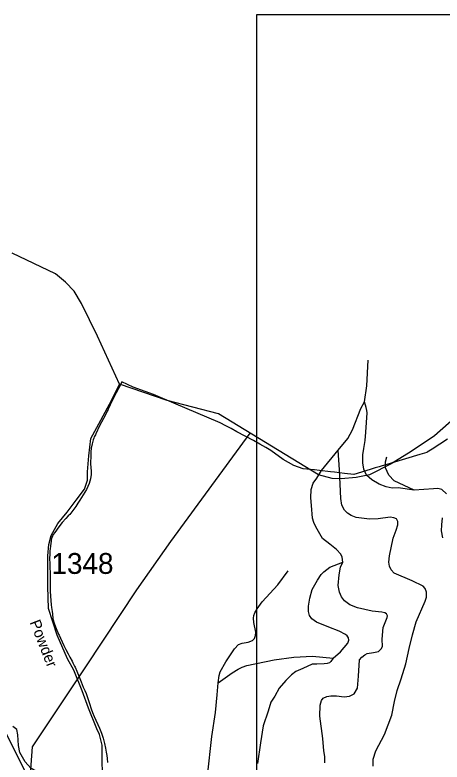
# Model space of a CAD drawing. Extents: x 884530 to 1028605, y 526725 to 653634.
# Drawn here: x 927572 to 930133, y 631169 to 635646 of the extents above; entities that cross this region are included whole.
import ezdxf

# ---------------------------------------------------------------- set-up
doc = ezdxf.new("R2010")
doc.units = 0
for name, color, linetype in [('Exist Boundary Political City Limit New', 7, 'Continuous'), ('Exist Boundary Political CountyLine', 7, 'Continuous'), ('Exist Hydrographic Creek Single Shore', 7, 'Continuous'), ('Exist Road Non-System Type 51', 7, 'Continuous'), ('Exist Road Secondary Type 51 Attributed', 7, 'Continuous'), ('Exist Road Secondary Type 51 Label', 7, 'Continuous'), ('Exist Road Secondary Type 51 Number Label', 7, 'Continuous'), ('Exist Utilities Electrical Transmission Line', 7, 'Continuous'), ('Map Preparation Boundary City Limit Buffer Line', 7, 'Continuous'), ('Map Preparation Inset Cut Line', 7, 'Continuous')]:
    doc.layers.add(name, color=color, linetype=linetype)

msp = doc.modelspace()

# ---------------------------------------------------------------- linework, layer by layer
at = {"layer": 'Exist Boundary Political City Limit New'}
for points in [[(929398.7, 632916.3), (929367.1, 632919.9), (929365.5, 632920.6), (929364.5, 632921.1), (929344, 632922.8), (929300.4, 632926.7), (929244.4, 632946.3), (929179.6, 632981.4), (929106.4, 633035.1), (929075.4, 633054.1), (929057.7, 633065), (929040.5, 633074.2), (929001.1, 633095.4), (928902.8, 633148.2), (928868.1, 633166.9), (928837.1, 633183.6), (928802.6, 633202.1), (928524, 633319.6), (928401.6, 633371.2), (928280.4, 633415.6), (928212.2, 633446.6), (928207.7, 633437.9), (928192.1, 633407.9), (928165.1, 633355.4), (928154.2, 633333.2), (928143.6, 633310.2), (928131.1, 633283.6), (928129.9, 633280.9), (928128.9, 633279.1), (928128.1, 633277.4), (928125.1, 633271.2), (928115, 633250.6), (928102.9, 633227.6), (928091.1, 633205.6), (928079.4, 633182.9), (928057, 633136.1), (928053.9, 633130.2), (928047.7, 633118.3), (928043.9, 633109.2), (928040.2, 633100.5), (928034, 633076.4), (928029.5, 633050.6), (928027.4, 633027.9), (928026.6, 633006.2), (928025.8, 632958.4), (928026.1, 632932.9), (928028.2, 632913.5), (928028.8, 632893.1), (928024.8, 632866.4), (928017.2, 632839), (928009.5, 632820.1), (928000.7, 632803), (927991, 632786.8), (927961.2, 632739.4), (927949.6, 632720.2), (927937.1, 632700.8), (927919.6, 632677.2), (927900.1, 632653.3), (927891.5, 632643.7), (927877.5, 632627.9), (927855.9, 632604), (927835.1, 632578.4), (927811, 632544.7), (927801.4, 632532.2), (927798.6, 632526.6), (927793.4, 632515.9), (927789.5, 632498.4), (927788, 632491.9), (927784.4, 632465.1), (927782.4, 632444), (927781.8, 632437.7), (927781.1, 632426.3), (927780.2, 632412.8), (927779.6, 632390.6), (927780.2, 632355.2), (927783, 632283.6), (927783.2, 632257.7), (927783.4, 632232.9), (927783.4, 632226.2), (927783.9, 632192.8), (927785.1, 632164), (927786.9, 632137), (927789.2, 632112), (927791, 632096.3), (927792.5, 632083.7), (927794, 632072.4), (927796.1, 632057.1), (927799.9, 632027.9), (927806.8, 632000.8), (927818.8, 631969.2), (927833.1, 631936.5), (927836.8, 631928.7), (927844.3, 631912.1), (927855, 631889.1), (927865.1, 631867.8), (927877, 631843.9), (927890.2, 631818.6), (927892.9, 631813.4), (927901.5, 631797.7), (927914.1, 631774)], [(930164.8, 633103.6), (930072.4, 633044.1), (930043.8, 633025.5), (930042.2, 633024.4), (930000, 633011.8), (929827.6, 632960.2), (929802.3, 632952.7), (929768.1, 632942.4), (929755.2, 632938.6), (929731.8, 632931.6), (929708.2, 632924.5), (929649.6, 632906.1), (929649.2, 632906.8), (929602.8, 632892.9), (929547.9, 632899.2), (929487.9, 632906.1), (929464.1, 632908.8), (929398.7, 632916.3)], [(927914.1, 631774), (927919.4, 631763.3), (927928.4, 631744.9), (927932.1, 631737.1), (927942.8, 631713.9), (927957, 631681), (927969.8, 631649.4), (927981.8, 631618.7), (927990.1, 631598.9), (927997.9, 631579.4), (928006.8, 631555.9), (928019.1, 631520.3), (928029.6, 631488.8), (928036.8, 631466.6), (928046.6, 631441.9), (928077.8, 631372.2), (928090.4, 631342.1), (928100.6, 631312.9), (928109.3, 631280.1), (928115.1, 631252.9), (928119.7, 631227.8), (928123.1, 631208.1), (928125.3, 631190.4), (928127.2, 631167.5)]]:
    msp.add_lwpolyline(points, dxfattribs=at)
at = {"layer": 'Exist Boundary Political CountyLine'}
for points in [[(929947.1, 633030.7), (929828.1, 632956.1), (929696.7, 632890.4), (929618.6, 632874.4), (929528.1, 632867.3), (929473.9, 632869.1), (929392.2, 632890.4), (928791.9, 633255.9), (928485, 633336.2), (928198.2, 633433.9), (928065.9, 633721.7), (927970.9, 633917.1), (927926.6, 633991.7), (927875.1, 634045), (927815.1, 634095.3), (927555.3, 634218.6)], [(932841.2, 631998.7), (932764.8, 632021.8), (932720.5, 632055.5), (932566, 632112.4), (932487.9, 632162.1), (932115, 632474.7), (932044.9, 632517.4), (931538, 632758.9), (931395.9, 632888.6), (930932.5, 633547.6), (930877.5, 633602.7), (930808.2, 633631.1), (930755, 633632.9), (930687.5, 633615.1), (930565, 633560), (930481.5, 633492.5), (930338.6, 633345.1), (930086.5, 633124.9), (929947.1, 633030.7)]]:
    msp.add_lwpolyline(points, dxfattribs=at)
at = {"layer": 'Exist Hydrographic Creek Single Shore'}
msp.add_lwpolyline([(927670.1, 630974.1), (927648.9, 631082.8), (927516.7, 631344.8), (927385.3, 631869.1), (927370, 632378.1), (927345.8, 632395), (927316.9, 632520.2), (927144.9, 632845.3), (927045.6, 633096.7), (926709.6, 633493.9), (926416, 634136.4), (926378.5, 634255.3), (926374.5, 634839.6), (926299.2, 635067.5)], dxfattribs=at)
at = {"layer": 'Exist Road Non-System Type 51'}
for points in [[(929667, 633328.4), (929681.9, 633424.2), (929689.3, 633576.8)], [(929510.5, 633037.6), (929566.8, 633107.1), (929595.8, 633159.9), (929644.9, 633287.2), (929667, 633328.4)], [(929965.6, 632797.9), (929869.9, 632811.5), (929833.8, 632810.6), (929796.5, 632817.4), (929755.4, 632834.4), (929711.4, 632860.8), (929679.7, 632889), (929663, 632923.3), (929656.7, 632962.9), (929658.1, 632990), (929656.6, 633010.6), (929664.1, 633047.6), (929671.1, 633095.8), (929675.4, 633145), (929683.3, 633261.9), (929681.9, 633276.4), (929677.6, 633294.7), (929667, 633328.4)], [(929537.1, 632368), (929534.1, 632396.7), (929525, 632414.9), (929499.2, 632443.9), (929459.2, 632475.5), (929415.8, 632509.8), (929375.4, 632578.5), (929363.4, 632605.7), (929356.7, 632630.6), (929349.5, 632706.4), (929345.5, 632753.3), (929348.7, 632802.4), (929360, 632840.3), (929381.7, 632871.3), (929410.4, 632917.1), (929510.5, 633037.6)], [(929719.8, 631144.7), (929719.1, 631185.9), (929736, 631236.6), (929786.7, 631333.7), (929831, 631450.7), (929846.8, 631532.9), (929864, 631597.8), (929887.9, 631668.9), (929916.3, 631757.4), (929935.9, 631850), (929954.4, 631931.4), (929976.4, 632010.5), (930030.9, 632133.2), (930038.9, 632158.2), (930038.9, 632187.3), (930031.1, 632210.1), (930019.2, 632223), (929953.6, 632256.1), (929845.2, 632301.7), (929826.7, 632321.1), (929818.3, 632342.6), (929813.9, 632367.2), (929817.2, 632404.6), (929839.7, 632511.4), (929856.7, 632557.9), (929867.2, 632591.4), (929867.2, 632611.6), (929859.3, 632626.6), (929842.6, 632633.6), (929820.6, 632636.3), (929748.8, 632627.2), (929698.1, 632624), (929617.2, 632635.5), (929588.1, 632646), (929565.2, 632660.1), (929547.6, 632677.7), (929531.7, 632707.6), (929525.5, 632748.8), (929522.5, 632833.4), (929516.8, 632920.9), (929510.5, 633037.6)], [(929965.6, 632797.9), (929846.3, 632854.9), (929812.7, 632887.7), (929794.1, 632931.4), (929793.7, 632967.2), (929802.2, 632997.6)], [(930159.2, 632776.9), (930131.7, 632802), (930106.7, 632807.8), (930081, 632806.3), (929965.6, 632797.9)], [(930137.6, 632512.1), (930129.3, 632554.7), (930130.9, 632591.6), (930135.4, 632632.7)], [(929479.2, 631791.1), (929523.3, 631830.6), (929568.1, 631881.7), (929572.9, 631899), (929572.5, 631913), (929564.4, 631924.9), (929554.2, 631933), (929515.9, 631953.9), (929453.4, 631977.7), (929380.3, 632007.6), (929352.1, 632027), (929338.1, 632047.3), (929331, 632071.9), (929331, 632102.7), (929339.2, 632150.8), (929354.4, 632202.7), (929385.3, 632259.1), (929407.5, 632292.4), (929422.9, 632310.1), (929459.1, 632337.8), (929537.1, 632368)], [(929430, 631165.7), (929429.1, 631203.5), (929424.6, 631237.6), (929417.5, 631310.9), (929399.9, 631444.8), (929401.6, 631510.4), (929409.8, 631538.7), (929419.3, 631552.3), (929442.1, 631563.1), (929466, 631566.6), (929499.2, 631566.6), (929545.2, 631560.4), (929577.5, 631564.4), (929605.8, 631578.3), (929625.5, 631613), (929632.2, 631684.4), (929636.9, 631781.3), (929651.1, 631798.6), (929668.7, 631812), (929684.4, 631819.7), (929721.7, 631825.5), (929751.4, 631832.7), (929768, 631847.5), (929776.3, 631862.1), (929773.4, 631905.9), (929780.4, 631976.3), (929804, 632036.3), (929804.9, 632046.2), (929798.5, 632057.8), (929789.7, 632063.1), (929771.2, 632067.5), (929713.1, 632073.6), (929625, 632093), (929580.1, 632112.4), (929548.5, 632135.3), (929530, 632159.1), (929518.5, 632188.1), (929510.6, 632226.9), (929515, 632290.2), (929522.9, 632336.9), (929537.1, 632368)], [(928789.6, 631644.1), (928796.1, 631687.8), (928803.2, 631710.8), (928836.7, 631769.8), (928863.5, 631811.2), (928888.3, 631847.2), (928911.3, 631873), (928934.2, 631881.6), (928969.3, 631887.7), (928995.5, 631897.1), (929008.7, 631910.1), (929014.7, 631928.4), (929016, 631947.1), (929003.8, 632005.2), (929002.5, 632032.2), (929004.4, 632047.3), (929009.6, 632063.9), (929024.6, 632087.8), (929054, 632128.6), (929147.6, 632232.1), (929210.3, 632315.7)], [(928789.6, 631644.1), (928874, 631703.8), (928910.3, 631726.2), (928934.2, 631738.4), (928962.7, 631747.7), (929126.4, 631781.3), (929244, 631798.5), (929355.9, 631804.3), (929479.2, 631791.1)], [(929479.2, 631791.1), (929466.6, 631772.5), (929458.2, 631764.6), (929443.3, 631759.5), (929426.5, 631758.5), (929381.7, 631756.3), (929353, 631755.5), (929298.5, 631729.7), (929255.4, 631712.5), (929229.6, 631692.4), (929195.3, 631658), (929155.1, 631612), (929129.2, 631563.3), (929106.3, 631528.9), (929089.1, 631474.4), (929060.4, 631385.5), (929043.2, 631285.1), (929026, 631161.7)], [(928835.2, 630588.3), (928843.3, 630597.1), (928845.5, 630603.1), (928840.6, 630616.8), (928802.6, 630682.1), (928754.2, 630773.1), (928759.8, 630923.9), (928734.2, 631020.6), (928725.8, 631086.1), (928752.3, 631322.5), (928773.3, 631465.9), (928784.6, 631572), (928789.6, 631644.1)]]:
    msp.add_lwpolyline(points, dxfattribs=at)
at = {"layer": 'Exist Road Secondary Type 51 Attributed'}
for points in [[(928098.3, 631027.7), (928094.4, 631178.7), (928094.4, 631270.1), (928078.5, 631333.7), (928062.6, 631369.4), (928012.2, 631492.3), (927973.9, 631596.2), (927924.2, 631719.7), (927886.9, 631788.4), (927824.3, 631929.7), (927772.7, 632088.7), (927768.8, 632221.7), (927768.8, 632404.5), (927774.3, 632472.9), (927788.7, 632527.7), (927828.4, 632599.2), (927884, 632666.8), (927939.5, 632738.3), (927989.4, 632805.4), (928007.8, 632857.7), (928007.1, 632909.2), (928015, 633004.5), (928026.9, 633107.8), (928074.6, 633195.3), (928138.1, 633314.5), (928198.2, 633433.9)], [(928058.6, 630705.8), (928003.8, 630784.8), (927963.4, 630849.7), (927933, 630882.1), (927876.3, 630926.6), (927845.9, 630955), (927817.6, 630989.4), (927793.3, 631038), (927779.1, 631062.4), (927756.9, 631080.6), (927710.3, 631106.9), (927667.8, 631133.3), (927633.4, 631171.7), (927601, 631226.4), (927592.9, 631269), (927588.9, 631331.8), (927582.8, 631364.2), (927558.5, 631382.4)]]:
    msp.add_lwpolyline(points, dxfattribs=at)
at = {"layer": 'Exist Utilities Electrical Transmission Line'}
msp.add_lwpolyline([(919215.5, 597808.3), (921124.3, 600075), (921355.3, 603059.1), (925357.2, 607735.8), (926768.3, 610919.4), (927159.2, 611823.9), (928300.4, 613120.2), (929404.2, 614372.6), (929377.4, 616031), (929346.3, 617714.4), (929345.2, 618021.6), (929852.2, 621210.3), (929810.4, 621334.5), (929197.7, 622629.2), (928034.6, 624800), (927482.4, 626024.4), (927504.2, 627587.8), (927629.3, 629272), (927654.5, 630965.2), (927677.4, 631260.1), (927996.2, 631739.4), (928303.4, 632200.5), (928506, 632490), (928981.9, 633140.2)], dxfattribs=at)
at = {"layer": 'Map Preparation Boundary City Limit Buffer Line'}
for points in [[(929398.7, 632916.3), (929367.1, 632919.9), (929365.5, 632920.6), (929364.5, 632921.1), (929344, 632922.8), (929300.4, 632926.7), (929244.4, 632946.3), (929179.6, 632981.4), (929106.4, 633035.1), (929075.4, 633054.1), (929057.7, 633065), (929040.5, 633074.2), (929001.1, 633095.4), (928902.8, 633148.2), (928868.1, 633166.9), (928837.1, 633183.6), (928802.6, 633202.1), (928524, 633319.6), (928401.6, 633371.2), (928280.4, 633415.6), (928212.2, 633446.6), (928207.7, 633437.9), (928192.1, 633407.9), (928165.1, 633355.4), (928154.2, 633333.2), (928143.6, 633310.2), (928131.1, 633283.6), (928129.9, 633280.9), (928128.9, 633279.1), (928128.1, 633277.4), (928125.1, 633271.2), (928115, 633250.6), (928102.9, 633227.6), (928091.1, 633205.6), (928079.4, 633182.9), (928057, 633136.1), (928053.9, 633130.2), (928047.7, 633118.3), (928043.9, 633109.2), (928040.2, 633100.5), (928034, 633076.4), (928029.5, 633050.6), (928027.4, 633027.9), (928026.6, 633006.2), (928025.8, 632958.4), (928026.1, 632932.9), (928028.2, 632913.5), (928028.8, 632893.1), (928024.8, 632866.4), (928017.2, 632839), (928009.5, 632820.1), (928000.7, 632803), (927991, 632786.8), (927961.2, 632739.4), (927949.6, 632720.2), (927937.1, 632700.8), (927919.6, 632677.2), (927900.1, 632653.3), (927891.5, 632643.7), (927877.5, 632627.9), (927855.9, 632604), (927835.1, 632578.4), (927811, 632544.7), (927801.4, 632532.2), (927798.6, 632526.6), (927793.4, 632515.9), (927789.5, 632498.4), (927788, 632491.9), (927784.4, 632465.1), (927782.4, 632444), (927781.8, 632437.7), (927781.1, 632426.3), (927780.2, 632412.8), (927779.6, 632390.6), (927780.2, 632355.2), (927783, 632283.6), (927783.2, 632257.7), (927783.4, 632232.9), (927783.4, 632226.2), (927783.9, 632192.8), (927785.1, 632164), (927786.9, 632137), (927789.2, 632112), (927791, 632096.3), (927792.5, 632083.7), (927794, 632072.4), (927796.1, 632057.1), (927799.9, 632027.9), (927806.8, 632000.8), (927818.8, 631969.2), (927833.1, 631936.5), (927836.8, 631928.7), (927844.3, 631912.1), (927855, 631889.1), (927865.1, 631867.8), (927877, 631843.9), (927890.2, 631818.6), (927892.9, 631813.4), (927901.5, 631797.7), (927914.1, 631774)], [(930164.8, 633103.6), (930072.4, 633044.1), (930043.8, 633025.5), (930042.2, 633024.4), (930000, 633011.8), (929827.6, 632960.2), (929802.3, 632952.7), (929768.1, 632942.4), (929755.2, 632938.6), (929731.8, 632931.6), (929708.2, 632924.5), (929649.6, 632906.1), (929649.2, 632906.8), (929602.8, 632892.9), (929547.9, 632899.2), (929487.9, 632906.1), (929464.1, 632908.8), (929398.7, 632916.3)], [(927914.1, 631774), (927919.4, 631763.3), (927928.4, 631744.9), (927932.1, 631737.1), (927942.8, 631713.9), (927957, 631681), (927969.8, 631649.4), (927981.8, 631618.7), (927990.1, 631598.9), (927997.9, 631579.4), (928006.8, 631555.9), (928019.1, 631520.3), (928029.6, 631488.8), (928036.8, 631466.6), (928046.6, 631441.9), (928077.8, 631372.2), (928090.4, 631342.1), (928100.6, 631312.9), (928109.3, 631280.1), (928115.1, 631252.9), (928119.7, 631227.8), (928123.1, 631208.1), (928125.3, 631190.4), (928127.2, 631167.5)]]:
    msp.add_lwpolyline(points, dxfattribs=at)
at = {"layer": 'Map Preparation Inset Cut Line'}
msp.add_lwpolyline([(929019.7, 608590.9), (973281.3, 608590.9), (973281.3, 635645.7), (929019.7, 635645.7)], close=True, dxfattribs=at)

# ---------------------------------------------------------------- texts
at = {"layer": 'Exist Road Secondary Type 51 Label'}
msp.add_text('Powder', height=65.62, rotation=291.4705, dxfattribs=at).set_placement((927659.4, 632006.9))
at = {"layer": 'Exist Road Secondary Type 51 Number Label'}
msp.add_text('1348', height=125, dxfattribs=at).set_placement((927790.8, 632296.8))

doc.saveas('drawing.dxf')
